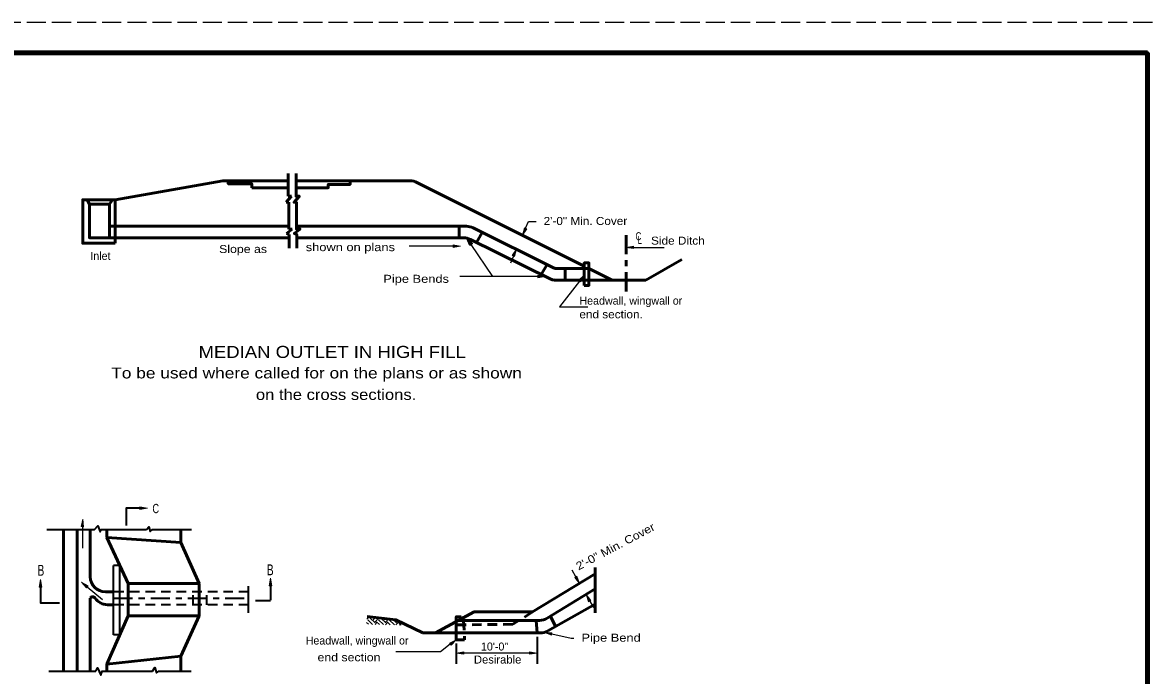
# Model space of a CAD drawing. Extents: x 36.1 to 71.5, y 0.2 to 22.2.
# Drawn here: x 52.56 to 71.34, y 11.37 to 22.21 of the extents above; entities that cross this region are included whole.
import ezdxf

# ---------------------------------------------------------------- set-up
doc = ezdxf.new("R2010")
doc.units = 0
doc.header["$LTSCALE"] = 0.053
doc.header["$PDMODE"] = 32
doc.header["$PDSIZE"] = 0.0265
for name, pattern in [('LONG_DASH_SHORT_DASH', [9.9, 6, -1.2, 1.5, -1.2]), ('LONG_DASHED', [7.5, 6, -1.5]), ('MEDIUM_DASHED', [4.5, 3, -1.5])]:
    doc.linetypes.add(name, pattern=pattern)
for name, color, linetype, lineweight in [('1', 7, 'Continuous', 35), ('2', 7, 'MEDIUM_DASHED', 53), ('3', 7, 'Continuous', 25), ('5', 7, 'Continuous', 35), ('6', 7, 'Continuous', 13), ('7', 7, 'LONG_DASH_SHORT_DASH', 35)]:
    doc.layers.add(name, color=color, linetype=linetype, lineweight=lineweight)

msp = doc.modelspace()

# ---------------------------------------------------------------- hatches: boundary and pattern name
at = {"layer": '1'}
for points in [[(60.93767, 18.78725), (60.8995, 18.804), (60.86858, 18.68108), (60.86858, 18.68108)], [(60.73525, 18.32408), (60.69708, 18.34075), (60.76625, 18.44692), (60.76625, 18.44692)], [(59.89025, 11.71658), (59.89025, 11.75825), (59.76525, 11.73742), (59.76525, 11.73742)], [(60.98458, 11.71658), (60.98458, 11.75825), (61.10958, 11.73742), (61.10958, 11.73742)]]:
    msp.add_hatch(color=256, dxfattribs=at).paths.add_polyline_path(points)
at = {"layer": '3'}
for points in [[(59.99358, 18.51642), (60.02825, 18.53967), (59.94133, 18.63183), (59.94133, 18.63183)], [(59.7125, 18.52), (59.7125, 18.47833), (59.8375, 18.49917), (59.8375, 18.49917)], [(62.713, 18.45675), (62.713, 18.49842), (62.588, 18.47758), (62.588, 18.47758)], [(61.12183, 18.015), (61.12183, 17.97333), (61.24683, 17.99417), (61.24683, 17.99417)], [(61.80017, 17.92942), (61.833, 17.90375), (61.8935, 18.01508), (61.8935, 18.01508)], [(53.53125, 13.83717), (53.57292, 13.8355), (53.55717, 13.96125), (53.55717, 13.96125)], [(61.736, 12.99292), (61.77217, 13.01367), (61.81608, 12.89475), (61.81608, 12.89475)], [(53.62017, 12.82083), (53.64667, 12.85292), (53.53717, 12.9165), (53.53717, 12.9165)], [(61.96692, 12.58917), (62.00308, 12.60983), (61.923, 12.708), (61.923, 12.708)], [(61.34833, 12.03358), (61.35692, 12.07442), (61.23033, 12.07983), (61.23033, 12.07983)], [(59.65367, 11.89867), (59.67917, 11.86575), (59.76525, 11.95867), (59.76525, 11.95867)]]:
    msp.add_hatch(color=256, dxfattribs=at).paths.add_polyline_path(points)
at = {"layer": '5'}
for points in [[(54.50808, 14.16458), (54.50808, 14.12292), (54.63308, 14.14375), (54.63308, 14.14375)], [(56.65692, 12.85342), (56.69858, 12.85342), (56.67775, 12.97842), (56.67775, 12.97842)], [(52.83408, 12.83258), (52.87575, 12.83258), (52.85492, 12.95758), (52.85492, 12.95758)]]:
    msp.add_hatch(color=256, dxfattribs=at).paths.add_polyline_path(points)

# ---------------------------------------------------------------- linework, layer by layer
at = {"layer": '1', "linetype": 'LONG_DASHED', "lineweight": 25}
msp.add_line((71.33717, 22.21317), (36.13717, 22.21317), dxfattribs=at)
at = {"layer": '1', "lineweight": 158}
for q in [(38.75383, 21.71317), (71.25383, 0.71317)]:
    msp.add_line((71.25383, 21.71317), q, dxfattribs=at)
at = {"layer": '1', "lineweight": 53}
for p, q in [((56.97475, 19.70317), (56.97475, 19.3275)), ((57.10408, 19.58392), (59.00117, 19.58392)), ((61.8935, 18.16642), (59.11308, 19.5575)), ((56.97475, 19.46958), (56.367, 19.46958)), ((53.63167, 19.26842), (53.66817, 19.19367)), ((54.05233, 19.26842), (54.00058, 19.19367)), ((57.02892, 19.3275), (56.94167, 19.2265)), ((56.94167, 19.2265), (56.98075, 19.2265)), ((56.97475, 19.3275), (57.02892, 19.3275)), ((56.98075, 19.2265), (56.98075, 18.7815)), ((56.98075, 18.82833), (54.00058, 18.82833)), ((57.04092, 18.7815), (56.94467, 18.70892)), ((56.98075, 18.7815), (57.04092, 18.7815)), ((59.934, 18.82833), (57.11008, 18.82833)), ((59.81192, 18.63733), (59.81192, 18.82833)), ((61.38433, 18.13917), (60.04492, 18.80233)), ((56.98675, 18.63733), (54.0955, 18.63733)), ((56.94467, 18.70892), (56.98675, 18.69308)), ((56.98675, 18.69308), (56.98675, 18.46267)), ((59.88925, 18.63733), (57.11608, 18.63733)), ((61.33967, 17.94825), (60.00025, 18.61133)), ((60.10117, 18.56142), (60.198, 18.7265)), ((63.51817, 18.27817), (62.91475, 17.93525)), ((61.17925, 18.02767), (61.27842, 18.19167)), ((61.97175, 18.12625), (61.43983, 18.12625)), ((61.57458, 17.93525), (61.57458, 18.12625)), ((62.3555, 17.93525), (61.97175, 18.12725)), ((62.91475, 17.93525), (61.39517, 17.93525)), ((53.23925, 11.43592), (53.23925, 13.78717)), ((53.46475, 13.78717), (53.46475, 11.43592)), ((53.68333, 13.00492), (53.68333, 13.78717)), ((53.95667, 13.65808), (53.95667, 13.78717)), ((55.18658, 13.573), (55.18658, 13.78717)), ((53.95667, 13.65808), (55.18658, 13.573)), ((54.312, 12.89108), (53.95667, 13.65808)), ((55.18658, 13.573), (55.494, 12.89108)), ((62.0765, 12.40383), (62.0765, 13.158)), ((55.494, 12.89108), (54.312, 12.89108)), ((54.312, 12.3535), (54.312, 12.89108)), ((55.494, 12.3535), (55.494, 12.89108)), ((62.0765, 12.80225), (61.2775, 12.31475)), ((53.68333, 11.43592), (53.68333, 12.64667)), ((53.93333, 12.75492), (54.06917, 12.75492)), ((53.96933, 12.53983), (54.06917, 12.53983)), ((62.0765, 12.54883), (61.28667, 12.10317)), ((54.312, 12.3535), (53.95667, 11.55067)), ((55.494, 12.3535), (54.312, 12.3535)), ((55.494, 12.3535), (55.18658, 11.68708)), ((61.14733, 12.27817), (59.80392, 12.27817)), ((61.10958, 12.07083), (61.09525, 12.27817)), ((61.41558, 12.17592), (61.33067, 12.34717)), ((59.21067, 12.07083), (61.16383, 12.07083)), ((53.95667, 11.55067), (55.18658, 11.68708)), ((55.18658, 11.43592), (55.18658, 11.68708)), ((53.95667, 11.43592), (53.95667, 11.55067))]:
    msp.add_line(p, q, dxfattribs=at)
at = {"layer": '1', "lineweight": 25}
for p, q in [((60.91858, 18.79558), (60.96867, 18.91017)), ((60.96867, 18.91017), (61.09367, 18.91017)), ((60.71617, 18.33242), (60.66608, 18.21783)), ((60.98458, 11.73742), (59.89025, 11.73742))]:
    msp.add_line(p, q, dxfattribs=at)
at = {"layer": '1', "lineweight": 13}
for p, q in [((60.896, 18.66908), (61.0335, 18.609)), ((60.79375, 18.43492), (60.93117, 18.37483)), ((61.85575, 12.91742), (61.97233, 12.98417)), ((61.96258, 12.73067), (62.07917, 12.79733)), ((58.30608, 12.21533), (58.275, 12.24642)), ((58.28033, 12.29733), (58.32233, 12.33925)), ((58.37425, 12.2135), (58.29642, 12.29133)), ((58.418, 12.23608), (58.32958, 12.32442)), ((58.35167, 12.32442), (58.36208, 12.33483)), ((58.38483, 12.29133), (58.42167, 12.32817)), ((58.41633, 12.21233), (58.44008, 12.23608)), ((58.418, 12.25817), (58.48133, 12.3215)), ((58.48783, 12.21042), (58.44008, 12.25817)), ((58.556, 12.2085), (58.47325, 12.29133)), ((58.59475, 12.23608), (58.51283, 12.318)), ((58.56158, 12.29133), (58.58067, 12.31042)), ((58.58842, 12.20767), (58.61683, 12.23608)), ((58.59475, 12.25817), (58.64033, 12.30375)), ((58.66958, 12.20542), (58.61683, 12.25817)), ((58.73767, 12.20358), (58.65, 12.29133)), ((58.7715, 12.23608), (58.71183, 12.29575)), ((58.73833, 12.29133), (58.73967, 12.29267)), ((58.7605, 12.203), (58.79358, 12.23608)), ((58.7715, 12.25817), (58.78967, 12.27633)), ((58.85125, 12.2005), (58.79358, 12.25817)), ((58.91517, 12.20292), (58.89142, 12.22667)), ((58.82508, 12.20117), (58.82675, 12.20292)), ((58.93258, 12.19825), (58.93817, 12.20383))]:
    msp.add_line(p, q, dxfattribs=at)
at = {"layer": '1'}
for p, q in [((52.95908, 13.78717), (53.75567, 13.78717)), ((54.06917, 12.04075), (54.06917, 13.18983)), ((56.31392, 12.40433), (56.31392, 12.84667)), ((54.17358, 12.04075), (54.06917, 12.04075)), ((59.76525, 11.89617), (59.76525, 11.55742)), ((61.10958, 12.00833), (61.10958, 11.55742)), ((52.99325, 11.43592), (53.7735, 11.43592))]:
    msp.add_line(p, q, dxfattribs=at)
at = {"layer": '1', "lineweight": 158}
msp.add_lwpolyline([(71.25383, 21.71317), (71.25383, 0.71317), (38.75383, 0.71317)], dxfattribs=at)
at = {"layer": '1', "lineweight": 53}
for points in [[(54.0955, 19.26842), (55.88425, 19.58392), (56.97475, 19.58392)], [(56.367, 19.46958), (56.367, 19.53583), (55.97583, 19.53583), (55.97583, 19.58392)], [(57.10408, 19.70317), (57.10408, 19.3275), (57.15825, 19.3275), (57.071, 19.2265), (57.11008, 19.2265), (57.11008, 18.7815), (57.17025, 18.7815), (57.074, 18.70892), (57.11608, 18.69308), (57.11608, 18.46267)], [(58.00067, 19.58392), (58.00067, 19.52325), (57.63958, 19.52325), (57.63958, 19.46958), (57.10408, 19.46958)], [(54.0955, 18.63733), (53.66817, 18.63733), (53.66817, 19.19367), (54.00058, 19.19367), (54.00058, 18.63733)], [(62.0765, 13.05358), (61.03325, 12.41958), (60.06475, 12.41958), (59.4215, 12.07083)], [(58.28517, 12.34342), (58.76108, 12.29025), (59.21067, 12.07083)], [(59.90508, 11.95867), (59.76525, 11.95867), (59.76525, 12.341), (59.85017, 12.341)]]:
    msp.add_lwpolyline(points, dxfattribs=at)
for points in [[(54.0955, 18.546), (54.0955, 19.26842), (53.55733, 19.26842), (53.55733, 18.546)], [(61.8935, 17.84683), (61.97175, 17.84683), (61.97175, 18.21933), (61.8935, 18.21933)]]:
    msp.add_lwpolyline(points, close=True, dxfattribs=at)
at = {"layer": '1', "lineweight": 13}
for points in [[(60.93767, 18.78725), (60.8995, 18.804), (60.86858, 18.68108), (60.86858, 18.68108)], [(60.73525, 18.32408), (60.69708, 18.34075), (60.76625, 18.44692), (60.76625, 18.44692)], [(59.89025, 11.71658), (59.89025, 11.75825), (59.76525, 11.73742), (59.76525, 11.73742)], [(60.98458, 11.71658), (60.98458, 11.75825), (61.10958, 11.73742), (61.10958, 11.73742)]]:
    msp.add_lwpolyline(points, close=True, dxfattribs=at)
at = {"layer": '1'}
for points in [[(53.75567, 13.78717), (53.80908, 13.85267), (53.848, 13.75308), (53.86642, 13.78717), (54.61658, 13.78717)], [(54.61658, 13.78717), (54.65808, 13.83467), (54.67758, 13.75458), (54.71617, 13.78717), (55.36425, 13.78717)], [(54.17358, 12.04075), (54.17358, 13.18983), (54.06917, 13.18983)], [(53.7735, 11.43592), (53.80125, 11.49192), (53.85767, 11.37067), (53.88217, 11.43592), (54.71592, 11.43592)], [(54.71592, 11.43592), (54.75775, 11.49667), (54.78133, 11.4085), (54.821, 11.43592), (55.35742, 11.43592)]]:
    msp.add_lwpolyline(points, dxfattribs=at)
at = {"layer": '1', "lineweight": 53}
for centre, radius, start, end in [((59.00117, 19.33392), 0.25, 63.42057, 90), ((59.934, 18.57833), 0.25, 63.66027, 90), ((59.88925, 18.38733), 0.25, 63.66027, 90), ((61.43983, 18.25125), 0.125, 243.66027, 270), ((61.39517, 18.06025), 0.125, 243.66027, 270), ((53.93333, 13.00492), 0.25, 180, 270), ((53.72358, 12.62783), 0.04439, 33.39224, 154.86749), ((53.96933, 12.78983), 0.25, 213.39224, 270), ((61.14733, 12.52817), 0.25, 270, 301.38901), ((61.16383, 12.32083), 0.25, 270, 299.43653)]:
    msp.add_arc(centre, radius, start, end, dxfattribs=at)
at = {"layer": '1'}
msp.add_point((71.25383, 21.71317), dxfattribs=at)
at = {"layer": '2', "lineweight": 35}
for p, q in [((56.31392, 12.75492), (54.06917, 12.75492)), ((55.39383, 12.53983), (55.39383, 12.75492)), ((55.62208, 12.53983), (55.62208, 12.75492)), ((56.31392, 12.53983), (54.06917, 12.53983))]:
    msp.add_line(p, q, dxfattribs=at)
at = {"layer": '2'}
for points in [[(61.03325, 12.41958), (60.70575, 12.21525), (59.66733, 12.20408)], [(59.85017, 12.341), (59.88608, 12.27633), (59.90508, 11.95867)]]:
    msp.add_lwpolyline(points, dxfattribs=at)
at = {"layer": '3'}
for p, q in [((59.7125, 18.49917), (58.985, 18.49917)), ((60.011, 18.528), (60.369, 17.99417)), ((62.713, 18.47758), (63.22325, 18.47758)), ((61.12183, 17.99417), (59.82742, 17.99417)), ((53.55208, 13.83633), (53.55575, 13.47775)), ((61.75408, 13.00325), (61.692, 13.11175)), ((53.6335, 12.83683), (53.88467, 12.62908)), ((61.985, 12.5995), (62.04708, 12.491))]:
    msp.add_line(p, q, dxfattribs=at)
at = {"layer": '3', "lineweight": 35}
msp.add_lwpolyline([(59.99358, 18.51642), (60.02825, 18.53967), (59.94133, 18.63183), (59.94133, 18.63183)], close=True, dxfattribs=at)
at = {"layer": '3', "lineweight": 13}
for points in [[(59.7125, 18.52), (59.7125, 18.47833), (59.8375, 18.49917), (59.8375, 18.49917)], [(62.713, 18.45675), (62.713, 18.49842), (62.588, 18.47758), (62.588, 18.47758)], [(61.12183, 18.015), (61.12183, 17.97333), (61.24683, 17.99417), (61.24683, 17.99417)], [(61.80017, 17.92942), (61.833, 17.90375), (61.8935, 18.01508), (61.8935, 18.01508)], [(53.53125, 13.83717), (53.57292, 13.8355), (53.55717, 13.96125), (53.55717, 13.96125)], [(61.736, 12.99292), (61.77217, 13.01367), (61.81608, 12.89475), (61.81608, 12.89475)], [(53.62017, 12.82083), (53.64667, 12.85292), (53.53717, 12.9165), (53.53717, 12.9165)], [(61.96692, 12.58917), (62.00308, 12.60983), (61.923, 12.708), (61.923, 12.708)], [(61.34833, 12.03358), (61.35692, 12.07442), (61.23033, 12.07983), (61.23033, 12.07983)], [(59.65367, 11.89867), (59.67917, 11.86575), (59.76525, 11.95867), (59.76525, 11.95867)]]:
    msp.add_lwpolyline(points, close=True, dxfattribs=at)
at = {"layer": '3'}
for points in [[(61.81658, 17.91658), (61.48225, 17.48892), (61.95358, 17.48892)], [(61.35258, 12.054), (61.677, 11.98542), (61.72267, 11.98542)], [(59.66642, 11.88225), (59.50658, 11.75867), (58.76267, 11.75867)]]:
    msp.add_lwpolyline(points, dxfattribs=at)
at = {"layer": '5'}
for p, q in [((56.67775, 12.8655), (56.67775, 12.6155)), ((56.67775, 12.60342), (56.4295, 12.60342))]:
    msp.add_line(p, q, dxfattribs=at)
for points in [[(54.54242, 14.14375), (54.27892, 14.14375), (54.27892, 13.85625)], [(52.85492, 12.83258), (52.85492, 12.57208), (53.17267, 12.57208)]]:
    msp.add_lwpolyline(points, dxfattribs=at)
at = {"layer": '5', "lineweight": 13}
for points in [[(54.50808, 14.16458), (54.50808, 14.12292), (54.63308, 14.14375), (54.63308, 14.14375)], [(56.65692, 12.85342), (56.69858, 12.85342), (56.67775, 12.97842), (56.67775, 12.97842)], [(52.83408, 12.83258), (52.87575, 12.83258), (52.85492, 12.95758), (52.85492, 12.95758)]]:
    msp.add_lwpolyline(points, close=True, dxfattribs=at)
at = {"layer": '6'}
for p, q in [((60.83875, 18.69408), (60.83883, 18.69408)), ((60.86858, 18.68108), (60.86867, 18.68108)), ((60.73642, 18.46), (60.7365, 18.46)), ((61.80142, 12.88642), (61.8015, 12.88642)), ((61.81608, 12.89475), (61.81617, 12.89475)), ((61.90833, 12.69958), (61.90842, 12.69958)), ((61.10958, 12.07083), (61.10967, 12.07083)), ((59.76525, 11.95867), (59.76533, 11.95867)), ((59.76525, 11.73742), (59.76533, 11.73742))]:
    msp.add_line(p, q, dxfattribs=at)
at = {"layer": '7', "lineweight": 53}
msp.add_line((62.588, 17.74683), (62.588, 18.70733), dxfattribs=at)
at = {"layer": '7'}
msp.add_line((54.06917, 12.64742), (56.31392, 12.64742), dxfattribs=at)

# ---------------------------------------------------------------- texts
at = {"layer": '1', "width": 1.1}
msp.add_text('2\'-0" Min. Cover', height=0.133, dxfattribs=at).set_placement((61.21867, 18.85017))
at = {"layer": '1'}
msp.add_text('10\'-0"', height=0.133, dxfattribs=at).set_placement((60.17617, 11.77858))
at = {"layer": '3'}
for s, height, width, p in [('C', 0.133, 0.75, (62.74575, 18.597)), ('L', 0.133, 0.75, (62.78075, 18.53583)), ('Side Ditch', 0.133, 1.1, (63.00425, 18.5235)), ('Slope as', 0.133, 1.15, (55.82442, 18.384)), ('shown on plans', 0.133, 1.2, (57.26475, 18.41508)), ('Pipe Bends', 0.133, 1.2, (58.55375, 17.88883)), ('end section.', 0.133, 1.1, (61.8125, 17.29958)), ('MEDIAN OUTLET IN HIGH FILL', 0.2, 1.15, (55.48225, 16.64075)), ('To be used where called for on the plans or as shown', 0.1792, 1.2, (54.0315, 16.3005)), ('on the cross sections.', 0.1792, 1.15, (56.43617, 15.94267)), ('Pipe Bend', 0.133, 1.2, (61.84767, 11.92542)), ('end section', 0.133, 1.15, (57.46, 11.59992)), ('Desirable', 0.133, 1.05, (60.05958, 11.56258))]:
    msp.add_text(s, height=height, dxfattribs=dict(at, width=width)).set_placement(p)
for s, p in [('Inlet', (53.68333, 18.27)), ('Headwall, wingwall or', (61.8125, 17.52625)), ('Headwall, wingwall or', (57.26292, 11.87858))]:
    msp.add_text(s, height=0.133, dxfattribs=at).set_placement(p)
at = {"layer": '3', "width": 1.15}
msp.add_text('2\'-0" Min. Cover', height=0.133, rotation=27.959, dxfattribs=at).set_placement((61.79925, 13.1085))
at = {"layer": '5'}
for s, height, width, p in [('C', 0.1536, 0.75, (54.71592, 14.06183)), ('B', 0.18, 0.7, (52.8065, 13.02217)), ('B', 0.18, 0.7, (56.61817, 13.02975))]:
    msp.add_text(s, height=height, dxfattribs=dict(at, width=width)).set_placement(p)

doc.saveas('drawing.dxf')
